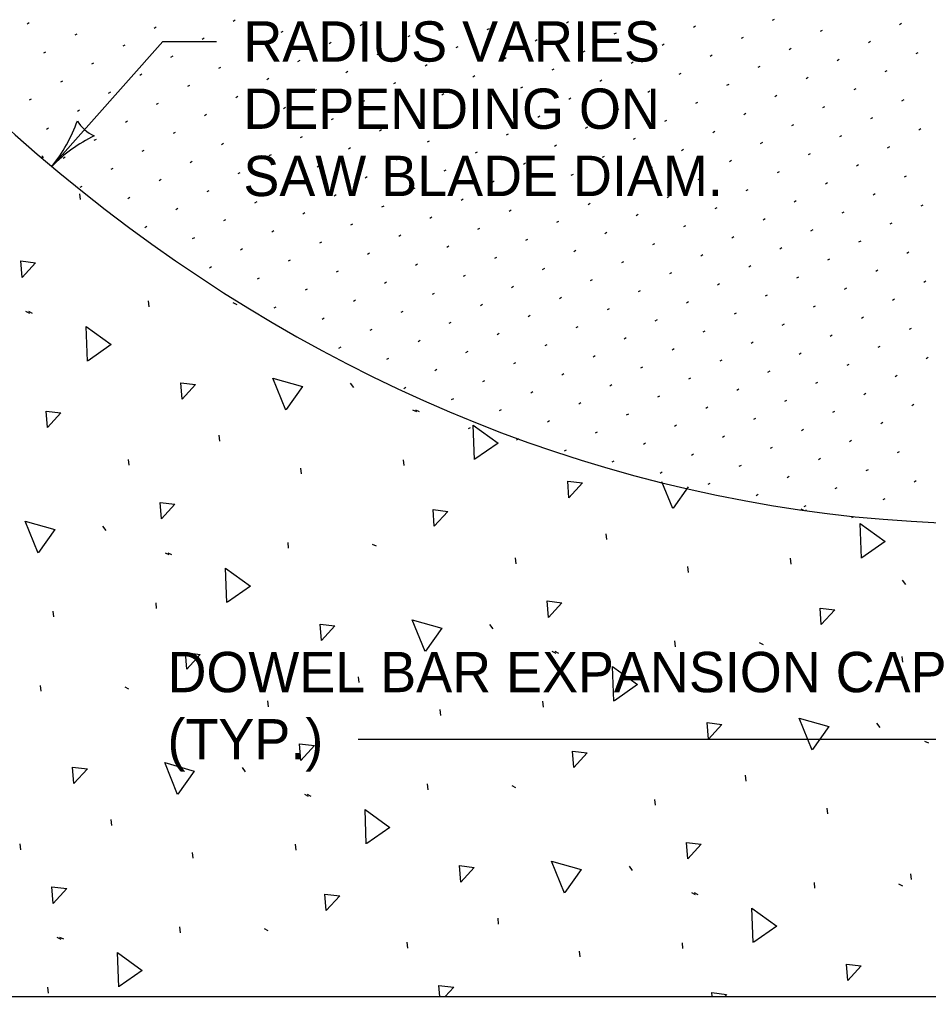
# Model space of a CAD drawing. Extents: x 49991.4 to 50021, y 49987.6 to 50011.4.
# Drawn here: x 50003.173 to 50004.525, y 49992.583 to 49994.036 of the extents above; entities that cross this region are included whole.
import ezdxf

# ---------------------------------------------------------------- set-up
doc = ezdxf.new("R2010")
doc.units = 0
for name, color, linetype in [('Level 1', 7, 'Continuous'), ('Level 2', 7, 'Continuous'), ('Level 3', 7, 'Continuous'), ('Level 4', 7, 'Continuous')]:
    doc.layers.add(name, color=color, linetype=linetype)

msp = doc.modelspace()

# ---------------------------------------------------------------- linework, layer by layer
at = {"layer": 'Level 1'}
msp.add_lwpolyline([(50001.9803, 49992.5827), (50004.606, 49992.5827), (50014.3713, 49992.5827)], dxfattribs=at)
msp.add_ellipse((50004.6259, 49996.2377), major_axis=(0, -2.952), ratio=0.83118, start_param=5.208402, end_param=6.283185, dxfattribs=at)
at = {"layer": 'Level 2'}
msp.add_line((50004.183, 49993.7981), (50004.1861, 49993.7999), dxfattribs=at)
at = {"layer": 'Level 3'}
for p, q in [((50004.2934, 49994.035), (50004.2964, 49994.0368)), ((50003.1843, 49994.0298), (50003.1873, 49994.0315)), ((50003.3733, 49994.0234), (50003.3764, 49994.0252)), ((50003.491, 49994.0336), (50003.494, 49994.0354)), ((50003.68, 49994.0273), (50003.683, 49994.029)), ((50003.869, 49994.021), (50003.8721, 49994.0227)), ((50003.9867, 49994.0312), (50003.9897, 49994.0329)), ((50004.1757, 49994.0248), (50004.1788, 49994.0266)), ((50004.4824, 49994.0287), (50004.4854, 49994.0304)), ((50003.2556, 49994.0132), (50003.2587, 49994.015)), ((50003.4447, 49994.0069), (50003.4477, 49994.0086)), ((50003.5623, 49994.0171), (50003.5654, 49994.0188)), ((50003.7514, 49994.0107), (50003.7544, 49994.0125)), ((50004.058, 49994.0146), (50004.0611, 49994.0164)), ((50004.2471, 49994.0083), (50004.2501, 49994.01)), ((50004.3647, 49994.0185), (50004.3678, 49994.0202)), ((50003.2212, 49993.8174), (50003.3861, 49994.0034)), ((50003.327, 49993.9967), (50003.33, 49993.9984)), ((50003.3861, 49994.0034), (50003.4661, 49994.0034)), ((50003.6337, 49994.0005), (50003.6367, 49994.0023)), ((50003.8227, 49993.9942), (50003.8257, 49993.996)), ((50003.9404, 49994.0044), (50003.9434, 49994.0062)), ((50004.1294, 49993.9981), (50004.1324, 49993.9998)), ((50004.3184, 49993.9917), (50004.3214, 49993.9935)), ((50004.4361, 49994.0019), (50004.4391, 49994.0037)), ((50003.2093, 49993.9865), (50003.2123, 49993.9882)), ((50003.3983, 49993.9801), (50003.4014, 49993.9819)), ((50003.516, 49993.9903), (50003.519, 49993.9921)), ((50003.705, 49993.984), (50003.708, 49993.9857)), ((50003.894, 49993.9777), (50003.8971, 49993.9794)), ((50004.0117, 49993.9879), (50004.0147, 49993.9896)), ((50004.2007, 49993.9815), (50004.2038, 49993.9833)), ((50004.5074, 49993.9854), (50004.5104, 49993.9871)), ((50003.2806, 49993.9699), (50003.2837, 49993.9717)), ((50003.4697, 49993.9636), (50003.4727, 49993.9653)), ((50003.5873, 49993.9738), (50003.5904, 49993.9755)), ((50003.7764, 49993.9674), (50003.7794, 49993.9692)), ((50004.083, 49993.9713), (50004.0861, 49993.9731)), ((50004.2721, 49993.965), (50004.2751, 49993.9667)), ((50004.3897, 49993.9752), (50004.3928, 49993.9769)), ((50003.352, 49993.9534), (50003.355, 49993.9551)), ((50003.541, 49993.947), (50003.544, 49993.9488)), ((50003.6587, 49993.9572), (50003.6617, 49993.959)), ((50003.8477, 49993.9509), (50003.8507, 49993.9526)), ((50003.9654, 49993.9611), (50003.9684, 49993.9629)), ((50004.1544, 49993.9548), (50004.1574, 49993.9565)), ((50004.3434, 49993.9484), (50004.3464, 49993.9502)), ((50004.4611, 49993.9586), (50004.4641, 49993.9604)), ((50003.2343, 49993.9432), (50003.2373, 49993.9449)), ((50003.4233, 49993.9368), (50003.4264, 49993.9386)), ((50003.73, 49993.9407), (50003.733, 49993.9424)), ((50003.919, 49993.9344), (50003.9221, 49993.9361)), ((50004.0367, 49993.9446), (50004.0397, 49993.9463)), ((50004.2257, 49993.9382), (50004.2288, 49993.94)), ((50003.3056, 49993.9266), (50003.3087, 49993.9284)), ((50003.4947, 49993.9203), (50003.4977, 49993.922)), ((50003.6123, 49993.9305), (50003.6154, 49993.9322)), ((50003.8014, 49993.9241), (50003.8044, 49993.9259)), ((50003.9904, 49993.9178), (50003.9934, 49993.9196)), ((50004.108, 49993.928), (50004.1111, 49993.9298)), ((50004.2971, 49993.9217), (50004.3001, 49993.9234)), ((50004.4147, 49993.9319), (50004.4178, 49993.9336)), ((50003.188, 49993.9164), (50003.191, 49993.9182)), ((50003.377, 49993.9101), (50003.38, 49993.9118)), ((50003.566, 49993.9037), (50003.569, 49993.9055)), ((50003.6837, 49993.9139), (50003.6867, 49993.9157)), ((50003.8727, 49993.9076), (50003.8757, 49993.9093)), ((50004.1794, 49993.9115), (50004.1824, 49993.9132)), ((50004.3684, 49993.9051), (50004.3714, 49993.9069)), ((50004.4861, 49993.9153), (50004.4891, 49993.9171)), ((50003.2593, 49993.8999), (50003.2623, 49993.9016)), ((50003.4483, 49993.8935), (50003.4514, 49993.8953)), ((50003.755, 49993.8974), (50003.758, 49993.8991)), ((50003.944, 49993.891), (50003.9471, 49993.8928)), ((50004.0617, 49993.9013), (50004.0647, 49993.903)), ((50004.2507, 49993.8949), (50004.2538, 49993.8967)), ((50003.3306, 49993.8833), (50003.3337, 49993.8851)), ((50003.5197, 49993.877), (50003.5227, 49993.8787)), ((50003.6373, 49993.8872), (50003.6404, 49993.8889)), ((50003.8264, 49993.8808), (50003.8294, 49993.8826)), ((50004.0154, 49993.8745), (50004.0184, 49993.8763)), ((50004.133, 49993.8847), (50004.1361, 49993.8865)), ((50004.3221, 49993.8784), (50004.3251, 49993.8801)), ((50004.4397, 49993.8886), (50004.4428, 49993.8903)), ((50003.213, 49993.8731), (50003.216, 49993.8749)), ((50003.402, 49993.8668), (50003.405, 49993.8685)), ((50003.591, 49993.8604), (50003.594, 49993.8622)), ((50003.7087, 49993.8706), (50003.7117, 49993.8724)), ((50003.8977, 49993.8643), (50003.9007, 49993.866)), ((50004.2044, 49993.8682), (50004.2074, 49993.8699)), ((50004.3934, 49993.8618), (50004.3964, 49993.8636)), ((50004.5111, 49993.872), (50004.5141, 49993.8738)), ((50003.2843, 49993.8566), (50003.2873, 49993.8583)), ((50003.4733, 49993.8502), (50003.4764, 49993.852)), ((50003.78, 49993.8541), (50003.783, 49993.8558)), ((50003.969, 49993.8477), (50003.9721, 49993.8495)), ((50004.0867, 49993.858), (50004.0897, 49993.8597)), ((50004.2757, 49993.8516), (50004.2788, 49993.8534)), ((50004.4647, 49993.8453), (50004.4678, 49993.847)), ((50003.3556, 49993.84), (50003.3587, 49993.8418)), ((50003.5447, 49993.8337), (50003.5477, 49993.8354)), ((50003.6623, 49993.8439), (50003.6654, 49993.8456)), ((50003.8514, 49993.8375), (50003.8544, 49993.8393)), ((50004.0404, 49993.8312), (50004.0434, 49993.833)), ((50004.158, 49993.8414), (50004.1611, 49993.8432)), ((50004.3471, 49993.8351), (50004.3501, 49993.8368)), ((50003.238, 49993.8298), (50003.241, 49993.8316)), ((50003.427, 49993.8235), (50003.43, 49993.8252)), ((50003.616, 49993.8171), (50003.619, 49993.8189)), ((50003.7337, 49993.8273), (50003.7367, 49993.8291)), ((50003.9227, 49993.821), (50003.9257, 49993.8227)), ((50004.2294, 49993.8249), (50004.2324, 49993.8266)), ((50004.4184, 49993.8185), (50004.4214, 49993.8203)), ((50003.3093, 49993.8133), (50003.3123, 49993.815)), ((50003.4983, 49993.8069), (50003.5014, 49993.8087)), ((50003.805, 49993.8108), (50003.808, 49993.8125)), ((50003.994, 49993.8044), (50003.9971, 49993.8062)), ((50004.1117, 49993.8147), (50004.1147, 49993.8164)), ((50004.3007, 49993.8083), (50004.3038, 49993.8101)), ((50004.4897, 49993.802), (50004.4928, 49993.8037)), ((50003.3806, 49993.7967), (50003.3837, 49993.7985)), ((50003.5697, 49993.7904), (50003.5727, 49993.7921)), ((50003.6873, 49993.8006), (50003.6904, 49993.8023)), ((50003.8764, 49993.7942), (50003.8794, 49993.796)), ((50004.0654, 49993.7879), (50004.0684, 49993.7896)), ((50004.3721, 49993.7918), (50004.3751, 49993.7935)), ((50003.263, 49993.7865), (50003.266, 49993.7883)), ((50003.452, 49993.7802), (50003.455, 49993.7819)), ((50003.641, 49993.7738), (50003.644, 49993.7756)), ((50003.7587, 49993.784), (50003.7617, 49993.7858)), ((50003.9477, 49993.7777), (50003.9507, 49993.7794)), ((50004.2544, 49993.7816), (50004.2574, 49993.7833)), ((50004.4434, 49993.7752), (50004.4464, 49993.777)), ((50003.3343, 49993.77), (50003.3373, 49993.7717)), ((50003.5233, 49993.7636), (50003.5264, 49993.7654)), ((50003.83, 49993.7675), (50003.833, 49993.7692)), ((50004.019, 49993.7611), (50004.0221, 49993.7629)), ((50004.1367, 49993.7714), (50004.1397, 49993.7731)), ((50004.3257, 49993.765), (50004.3288, 49993.7668)), ((50004.5147, 49993.7587), (50004.5178, 49993.7604)), ((50003.4056, 49993.7534), (50003.4087, 49993.7552)), ((50003.5947, 49993.7471), (50003.5977, 49993.7488)), ((50003.7123, 49993.7573), (50003.7154, 49993.759)), ((50003.9014, 49993.7509), (50003.9044, 49993.7527)), ((50004.0904, 49993.7446), (50004.0934, 49993.7463)), ((50004.208, 49993.7548), (50004.2111, 49993.7566)), ((50004.3971, 49993.7485), (50004.4001, 49993.7502)), ((50003.477, 49993.7369), (50003.48, 49993.7386)), ((50003.666, 49993.7305), (50003.669, 49993.7323)), ((50003.7837, 49993.7407), (50003.7867, 49993.7425)), ((50003.9727, 49993.7344), (50003.9757, 49993.7361)), ((50004.2794, 49993.7383), (50004.2824, 49993.74)), ((50004.4684, 49993.7319), (50004.4714, 49993.7337)), ((50003.3593, 49993.7267), (50003.3623, 49993.7284)), ((50003.5483, 49993.7203), (50003.5514, 49993.7221)), ((50003.855, 49993.7242), (50003.858, 49993.7259)), ((50004.044, 49993.7178), (50004.0471, 49993.7196)), ((50004.1617, 49993.7281), (50004.1647, 49993.7298)), ((50004.3507, 49993.7217), (50004.3538, 49993.7235)), ((50003.4306, 49993.7101), (50003.4337, 49993.7119)), ((50003.6197, 49993.7038), (50003.6227, 49993.7055)), ((50003.7373, 49993.714), (50003.7404, 49993.7157)), ((50003.9264, 49993.7076), (50003.9294, 49993.7094)), ((50004.1154, 49993.7013), (50004.1184, 49993.703)), ((50004.233, 49993.7115), (50004.2361, 49993.7133)), ((50004.4221, 49993.7052), (50004.4251, 49993.7069)), ((50003.502, 49993.6936), (50003.505, 49993.6953)), ((50003.691, 49993.6872), (50003.694, 49993.689)), ((50003.8087, 49993.6974), (50003.8117, 49993.6992)), ((50003.9977, 49993.6911), (50004.0007, 49993.6928)), ((50004.3044, 49993.695), (50004.3074, 49993.6967)), ((50004.4934, 49993.6886), (50004.4964, 49993.6904)), ((50003.5733, 49993.677), (50003.5764, 49993.6788)), ((50003.7623, 49993.6707), (50003.7654, 49993.6724)), ((50003.88, 49993.6809), (50003.883, 49993.6826)), ((50004.069, 49993.6745), (50004.0721, 49993.6763)), ((50004.1867, 49993.6847), (50004.1897, 49993.6865)), ((50004.3757, 49993.6784), (50004.3788, 49993.6802)), ((50003.4556, 49993.6668), (50003.4587, 49993.6686)), ((50003.6447, 49993.6605), (50003.6477, 49993.6622)), ((50003.9514, 49993.6643), (50003.9544, 49993.6661)), ((50004.1404, 49993.658), (50004.1434, 49993.6597)), ((50004.258, 49993.6682), (50004.2611, 49993.67)), ((50004.4471, 49993.6619), (50004.4501, 49993.6636)), ((50003.527, 49993.6503), (50003.53, 49993.652)), ((50003.716, 49993.6439), (50003.719, 49993.6457)), ((50003.8337, 49993.6541), (50003.8367, 49993.6559)), ((50004.0227, 49993.6478), (50004.0257, 49993.6495)), ((50004.3294, 49993.6517), (50004.3324, 49993.6534)), ((50004.5184, 49993.6453), (50004.5214, 49993.6471)), ((50003.5983, 49993.6337), (50003.6014, 49993.6355)), ((50003.7873, 49993.6274), (50003.7904, 49993.6291)), ((50003.905, 49993.6376), (50003.908, 49993.6393)), ((50004.094, 49993.6312), (50004.0971, 49993.633)), ((50004.2117, 49993.6414), (50004.2147, 49993.6432)), ((50004.4007, 49993.6351), (50004.4038, 49993.6369)), ((50003.6697, 49993.6172), (50003.6727, 49993.6189)), ((50003.9764, 49993.621), (50003.9794, 49993.6228)), ((50004.1654, 49993.6147), (50004.1684, 49993.6164)), ((50004.283, 49993.6249), (50004.2861, 49993.6267)), ((50004.4721, 49993.6186), (50004.4751, 49993.6203)), ((50003.552, 49993.607), (50003.555, 49993.6087)), ((50003.741, 49993.6006), (50003.744, 49993.6024)), ((50003.8587, 49993.6108), (50003.8617, 49993.6126)), ((50004.0477, 49993.6045), (50004.0507, 49993.6062)), ((50004.2367, 49993.5981), (50004.2397, 49993.5999)), ((50004.3544, 49993.6084), (50004.3574, 49993.6101)), ((50003.6233, 49993.5904), (50003.6264, 49993.5922)), ((50003.8123, 49993.5841), (50003.8154, 49993.5858)), ((50003.93, 49993.5943), (50003.933, 49993.596)), ((50004.119, 49993.5879), (50004.1221, 49993.5897)), ((50004.4257, 49993.5918), (50004.4288, 49993.5936)), ((50003.6947, 49993.5739), (50003.6977, 49993.5756)), ((50004.0014, 49993.5777), (50004.0044, 49993.5795)), ((50004.1904, 49993.5714), (50004.1934, 49993.5731)), ((50004.308, 49993.5816), (50004.3111, 49993.5833)), ((50004.4971, 49993.5753), (50004.5001, 49993.577)), ((50003.766, 49993.5573), (50003.769, 49993.5591)), ((50003.8837, 49993.5675), (50003.8867, 49993.5693)), ((50004.0727, 49993.5612), (50004.0757, 49993.5629)), ((50004.2617, 49993.5548), (50004.2647, 49993.5566)), ((50004.3794, 49993.5651), (50004.3824, 49993.5668)), ((50003.6483, 49993.5471), (50003.6514, 49993.5489)), ((50003.8373, 49993.5408), (50003.8404, 49993.5425)), ((50003.955, 49993.551), (50003.958, 49993.5527)), ((50004.144, 49993.5446), (50004.1471, 49993.5464)), ((50004.4507, 49993.5485), (50004.4538, 49993.5503)), ((50003.7197, 49993.5306), (50003.7227, 49993.5323)), ((50004.0264, 49993.5344), (50004.0294, 49993.5362)), ((50004.2154, 49993.5281), (50004.2184, 49993.5298)), ((50004.333, 49993.5383), (50004.3361, 49993.54)), ((50004.5221, 49993.532), (50004.5251, 49993.5337)), ((50003.791, 49993.514), (50003.794, 49993.5158)), ((50003.9087, 49993.5242), (50003.9117, 49993.526)), ((50004.0977, 49993.5179), (50004.1007, 49993.5196)), ((50004.2867, 49993.5115), (50004.2897, 49993.5133)), ((50004.4044, 49993.5217), (50004.4074, 49993.5235)), ((50003.8623, 49993.4975), (50003.8654, 49993.4992)), ((50003.98, 49993.5077), (50003.983, 49993.5094)), ((50004.169, 49993.5013), (50004.1721, 49993.5031)), ((50004.4757, 49993.5052), (50004.4788, 49993.507)), ((50003.7447, 49993.4873), (50003.7477, 49993.489)), ((50004.0514, 49993.4911), (50004.0544, 49993.4929)), ((50004.2404, 49993.4848), (50004.2434, 49993.4865)), ((50004.358, 49993.495), (50004.3611, 49993.4967)), ((50003.816, 49993.4707), (50003.819, 49993.4725)), ((50003.9337, 49993.4809), (50003.9367, 49993.4827)), ((50004.1227, 49993.4746), (50004.1257, 49993.4763)), ((50004.3117, 49993.4682), (50004.3147, 49993.47)), ((50004.4294, 49993.4784), (50004.4324, 49993.4802)), ((50003.8873, 49993.4542), (50003.8904, 49993.4559)), ((50004.005, 49993.4644), (50004.008, 49993.4661)), ((50004.194, 49993.458), (50004.1971, 49993.4598)), ((50004.5007, 49993.4619), (50004.5038, 49993.4637)), ((50004.0764, 49993.4478), (50004.0794, 49993.4496)), ((50004.2654, 49993.4415), (50004.2684, 49993.4432)), ((50004.383, 49993.4517), (50004.3861, 49993.4534)), ((50003.841, 49993.4274), (50003.844, 49993.4292)), ((50003.9587, 49993.4376), (50003.9617, 49993.4394)), ((50004.1477, 49993.4313), (50004.1507, 49993.433)), ((50004.3367, 49993.4249), (50004.3397, 49993.4267)), ((50004.4544, 49993.4351), (50004.4574, 49993.4369)), ((50003.9123, 49993.4109), (50003.9154, 49993.4126)), ((50004.03, 49993.4211), (50004.033, 49993.4228)), ((50004.219, 49993.4147), (50004.2221, 49993.4165)), ((50004.1014, 49993.4045), (50004.1044, 49993.4063)), ((50004.2904, 49993.3982), (50004.2934, 49993.3999)), ((50004.408, 49993.4084), (50004.4111, 49993.4101)), ((50003.9837, 49993.3943), (50003.9867, 49993.3961)), ((50004.1727, 49993.388), (50004.1757, 49993.3897)), ((50004.3617, 49993.3816), (50004.3647, 49993.3834)), ((50004.4794, 49993.3918), (50004.4824, 49993.3936)), ((50004.055, 49993.3778), (50004.058, 49993.3795)), ((50004.244, 49993.3714), (50004.2471, 49993.3732)), ((50004.1264, 49993.3612), (50004.1294, 49993.363)), ((50004.3154, 49993.3549), (50004.3184, 49993.3566)), ((50004.433, 49993.3651), (50004.4361, 49993.3668)), ((50004.1977, 49993.3447), (50004.2007, 49993.3464)), ((50004.3867, 49993.3383), (50004.3897, 49993.3401)), ((50004.5044, 49993.3485), (50004.5074, 49993.3503)), ((50004.269, 49993.3281), (50004.2721, 49993.3299)), ((50004.3404, 49993.3116), (50004.3434, 49993.3133)), ((50004.458, 49993.3218), (50004.4611, 49993.3235)), ((50004.4117, 49993.295), (50004.4147, 49993.2968)), ((50003.6769, 49992.9653), (50004.7013, 49992.9653))]:
    msp.add_line(p, q, dxfattribs=at)
for centre, radius, start, end in [((50003.0394, 49993.9631), 0.233, 321.2826, 340.5324), ((50003.3062, 49993.9133), 0.0548, 210.5941, 246.3164), ((50003.3814, 49993.6632), 0.2223, 115.9113, 136.0948)]:
    msp.add_arc(centre, radius, start, end, dxfattribs=at)
at = {"layer": 'Level 4'}
for p, q in [((50003.2637, 49993.7682), (50003.2627, 49993.7769)), ((50003.366, 49993.6087), (50003.3651, 49993.6174)), ((50003.4905, 49993.615), (50003.4963, 49993.6121)), ((50003.1821, 49993.6021), (50003.1878, 49993.5993)), ((50003.1862, 49993.6022), (50003.1919, 49993.5993)), ((50003.6651, 49993.4952), (50003.6698, 49993.4887)), ((50003.7579, 49993.4556), (50003.7636, 49993.4527)), ((50003.762, 49993.4556), (50003.7677, 49993.4528)), ((50003.4711, 49993.4089), (50003.4701, 49993.4176)), ((50003.336, 49993.373), (50003.335, 49993.3817)), ((50003.5925, 49993.3601), (50003.5916, 49993.3688)), ((50003.7454, 49993.3724), (50003.7445, 49993.3811)), ((50004.3357, 49993.3081), (50004.3394, 49993.3062)), ((50004.3425, 49993.3067), (50004.3435, 49993.3062)), ((50003.2967, 49993.2825), (50003.3014, 49993.276)), ((50004.0469, 49993.2624), (50004.0459, 49993.2711)), ((50003.5734, 49993.2495), (50003.5725, 49993.2582)), ((50003.6979, 49993.2557), (50003.7037, 49993.2529)), ((50003.3895, 49993.2429), (50003.3953, 49993.2401)), ((50003.3936, 49993.2429), (50003.3993, 49993.2401)), ((50003.9118, 49993.2264), (50003.9108, 49993.2351)), ((50004.1683, 49993.2136), (50004.1674, 49993.2223)), ((50004.3212, 49993.2258), (50004.3203, 49993.2345)), ((50004.4866, 49993.2021), (50004.4914, 49993.1956)), ((50003.377, 49993.1597), (50003.3761, 49993.1684)), ((50003.2242, 49993.1474), (50003.2232, 49993.1561)), ((50003.8725, 49993.1359), (50003.8772, 49993.1295)), ((50004.1492, 49993.1029), (50004.1483, 49993.1116)), ((50004.2737, 49993.1092), (50004.2795, 49993.1064)), ((50003.9653, 49993.0963), (50003.971, 49993.0935)), ((50003.9694, 49993.0964), (50003.9751, 49993.0935)), ((50004.4875, 49993.0799), (50004.4866, 49993.0886)), ((50003.6785, 49993.0497), (50003.6775, 49993.0584)), ((50003.205, 49993.0368), (50003.2041, 49993.0455)), ((50003.3295, 49993.0431), (50003.3353, 49993.0402)), ((50003.5434, 49993.0137), (50003.5424, 49993.0224)), ((50003.9528, 49993.0131), (50003.9519, 49993.0218)), ((50003.8, 49993.0009), (50003.799, 49993.0096)), ((50004.4483, 49992.9894), (50004.453, 49992.9829)), ((50004.5195, 49992.9626), (50004.5253, 49992.9598)), ((50003.5041, 49992.9232), (50003.5088, 49992.9168)), ((50004.2543, 49992.9031), (50004.2533, 49992.9118)), ((50003.7808, 49992.8902), (50003.7799, 49992.8989)), ((50003.9053, 49992.8965), (50003.9111, 49992.8937)), ((50003.5969, 49992.8837), (50003.6027, 49992.8808)), ((50003.601, 49992.8837), (50003.6067, 49992.8808)), ((50004.1192, 49992.8672), (50004.1182, 49992.8759)), ((50004.3757, 49992.8543), (50004.3748, 49992.863)), ((50003.3101, 49992.837), (50003.3092, 49992.8457)), ((50003.175, 49992.801), (50003.1741, 49992.8097)), ((50003.5845, 49992.8005), (50003.5835, 49992.8091)), ((50003.4316, 49992.7882), (50003.4306, 49992.7969)), ((50004.0799, 49992.7767), (50004.0846, 49992.7702)), ((50004.5001, 49992.7566), (50004.4991, 49992.7653)), ((50004.3566, 49992.7437), (50004.3557, 49992.7524)), ((50004.4811, 49992.75), (50004.4869, 49992.7471)), ((50004.1727, 49992.7371), (50004.1785, 49992.7343)), ((50004.1768, 49992.7371), (50004.1825, 49992.7343)), ((50003.8859, 49992.6904), (50003.885, 49992.6991)), ((50003.4124, 49992.6775), (50003.4115, 49992.6862)), ((50003.2285, 49992.671), (50003.2343, 49992.6681)), ((50003.2326, 49992.671), (50003.2384, 49992.6682)), ((50003.5369, 49992.6838), (50003.5427, 49992.681)), ((50003.7508, 49992.6545), (50003.7499, 49992.6632)), ((50004.1602, 49992.6539), (50004.1593, 49992.6626)), ((50004.0074, 49992.6416), (50004.0064, 49992.6503)), ((50003.2161, 49992.5878), (50003.2151, 49992.5965))]:
    msp.add_line(p, q, dxfattribs=at)
for points in [[(50003.2073, 49993.8305), (50003.2071, 49993.8332)], [(50003.2087, 49993.832), (50003.2073, 49993.8305)], [(50003.1767, 49993.6523), (50003.1748, 49993.6769), (50003.1969, 49993.6742), (50003.1767, 49993.6523)], [(50003.2741, 49993.528), (50003.2723, 49993.5792), (50003.3093, 49993.5524), (50003.2749, 49993.5284)], [(50003.5692, 49993.455), (50003.5499, 49993.5025), (50003.5939, 49993.4899), (50003.5698, 49993.4557)], [(50003.4148, 49993.4713), (50003.4129, 49993.4958), (50003.4349, 49993.4932), (50003.4148, 49993.4713)], [(50003.2144, 49993.4289), (50003.2126, 49993.4535), (50003.2346, 49993.4508), (50003.2144, 49993.4289)], [(50003.8499, 49993.3814), (50003.8481, 49993.4327), (50003.8851, 49993.4058), (50003.8507, 49993.3819)], [(50003.9905, 49993.3247), (50003.9887, 49993.3493), (50004.0107, 49993.3466), (50003.9905, 49993.3247)], [(50004.145, 49993.3084), (50004.1287, 49993.3485)], [(50004.1679, 49993.3408), (50004.1456, 49993.3091)], [(50003.3841, 49993.2931), (50003.3822, 49993.3177), (50003.4043, 49993.315), (50003.3841, 49993.2931)], [(50003.7902, 49993.2824), (50003.7883, 49993.3069), (50003.8104, 49993.3043), (50003.7902, 49993.2824)], [(50003.2008, 49993.2423), (50003.1815, 49993.2898), (50003.2255, 49993.2772), (50003.2014, 49993.243)], [(50004.4257, 49993.2349), (50004.4238, 49993.2861), (50004.4609, 49993.2593), (50004.4265, 49993.2353)], [(50003.4815, 49993.1688), (50003.4797, 49993.22), (50003.5167, 49993.1931), (50003.4823, 49993.1692)], [(50003.9599, 49993.1466), (50003.958, 49993.1711), (50003.9801, 49993.1684), (50003.9599, 49993.1466)], [(50004.366, 49993.1358), (50004.3641, 49993.1604), (50004.3862, 49993.1577), (50004.366, 49993.1358)], [(50003.6222, 49993.112), (50003.6203, 49993.1366), (50003.6423, 49993.1339), (50003.6222, 49993.112)], [(50003.7766, 49993.0957), (50003.7573, 49993.1432), (50003.8013, 49993.1307), (50003.7772, 49993.0964)], [(50003.4218, 49993.0697), (50003.42, 49993.0942), (50003.442, 49993.0916), (50003.4218, 49993.0697)], [(50004.0573, 49993.0222), (50004.0555, 49993.0734), (50004.0925, 49993.0466), (50004.0581, 49993.0226)], [(50004.198, 49992.9655), (50004.1961, 49992.99), (50004.2181, 49992.9874), (50004.198, 49992.9655)], [(50004.3524, 49992.9492), (50004.3331, 49992.9967), (50004.3771, 49992.9841), (50004.353, 49992.9499)], [(50003.5915, 49992.9339), (50003.5897, 49992.9584), (50003.6117, 49992.9558), (50003.5915, 49992.9339)], [(50003.9976, 49992.9231), (50003.9958, 49992.9477), (50004.0178, 49992.945), (50003.9976, 49992.9231)], [(50003.2538, 49992.8994), (50003.2519, 49992.9239), (50003.2739, 49992.9213), (50003.2538, 49992.8994)], [(50003.4082, 49992.8831), (50003.389, 49992.9305), (50003.4329, 49992.918), (50003.4088, 49992.8837)], [(50003.689, 49992.8095), (50003.6871, 49992.8607), (50003.7241, 49992.8339), (50003.6897, 49992.81)], [(50004.1673, 49992.7873), (50004.1654, 49992.8119), (50004.1875, 49992.8092), (50004.1673, 49992.7873)], [(50003.8296, 49992.7528), (50003.8277, 49992.7774), (50003.8497, 49992.7747), (50003.8296, 49992.7528)], [(50003.984, 49992.7365), (50003.9647, 49992.784), (50004.0087, 49992.7714), (50003.9846, 49992.7372)], [(50003.2231, 49992.7212), (50003.2213, 49992.7457), (50003.2433, 49992.7431), (50003.2231, 49992.7212)], [(50003.6292, 49992.7104), (50003.6274, 49992.735), (50003.6494, 49992.7323), (50003.6292, 49992.7104)], [(50004.2647, 49992.663), (50004.2629, 49992.7142), (50004.2999, 49992.6874), (50004.2655, 49992.6634)], [(50003.3206, 49992.5968), (50003.3187, 49992.648), (50003.3557, 49992.6212), (50003.3213, 49992.5973)], [(50004.4054, 49992.6062), (50004.4035, 49992.6308), (50004.4255, 49992.6281), (50004.4054, 49992.6062)], [(50003.7983, 49992.5827), (50003.7971, 49992.5992), (50003.8191, 49992.5965), (50003.8063, 49992.5827)], [(50004.2036, 49992.5827), (50004.2032, 49992.5884), (50004.2252, 49992.5858), (50004.2223, 49992.5827)]]:
    msp.add_lwpolyline(points, dxfattribs=at)

# ---------------------------------------------------------------- texts
at = {"layer": 'Level 2'}
for s, p in [('RADIUS VARIES', (50003.5061, 49993.9734)), ('DEPENDING ON', (50003.5061, 49993.8734)), ('SAW BLADE DIAM.', (50003.5061, 49993.7734)), ('DOWEL BAR EXPANSION CAP', (50003.3932, 49993.0353)), ('(TYP.)', (50003.3932, 49992.9353))]:
    msp.add_text(s, height=0.06, dxfattribs=at).set_placement(p)

doc.saveas('drawing.dxf')
